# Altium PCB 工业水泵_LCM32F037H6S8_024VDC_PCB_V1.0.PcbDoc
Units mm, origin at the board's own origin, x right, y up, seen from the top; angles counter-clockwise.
Board outline 152.4 x 101.6 mm, 2 copper layers (Top Layer, Bottom Layer); 70 components, 49 nets, 180 pads, 167 vias.
Unrouted connection lines stored in the file: 17.
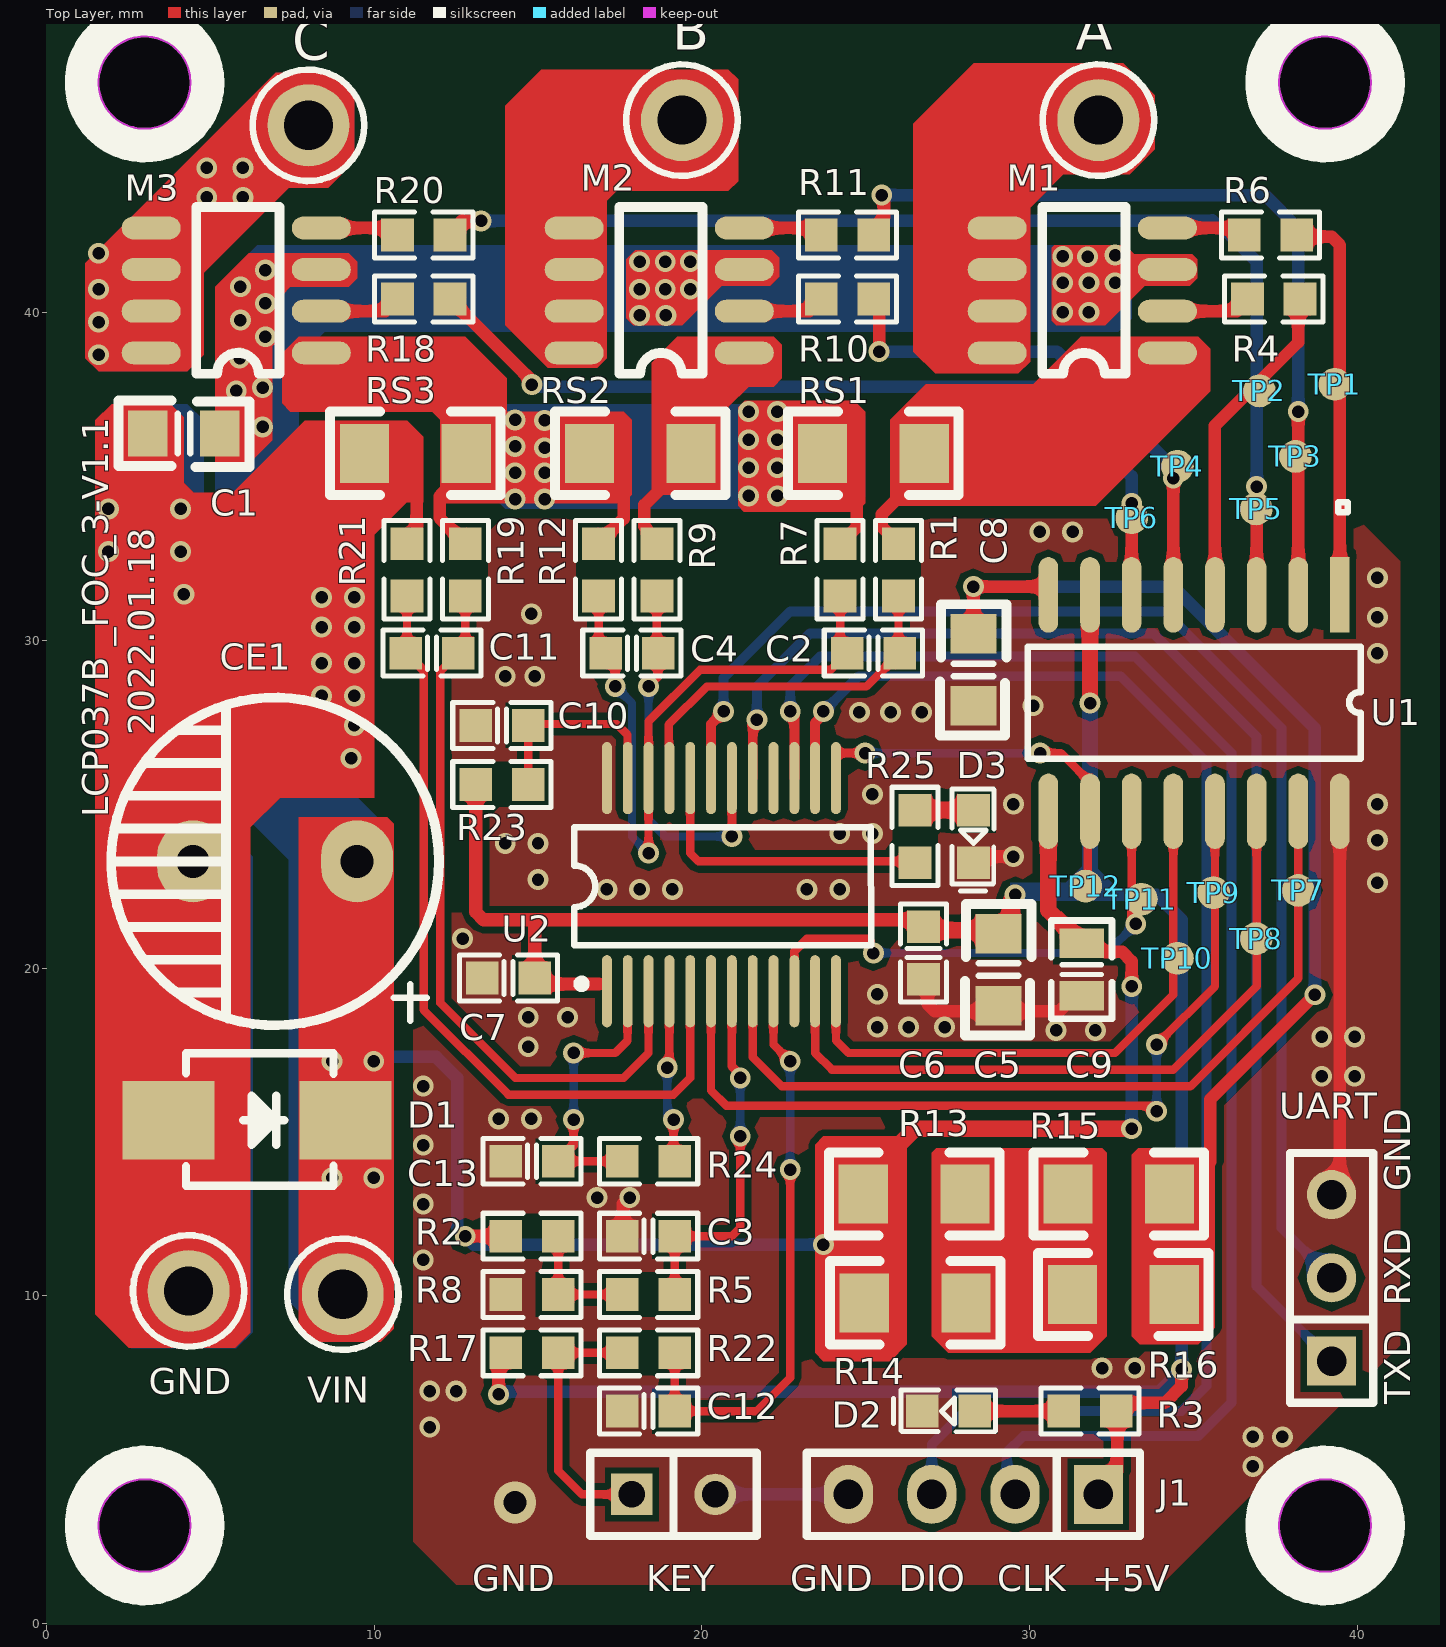
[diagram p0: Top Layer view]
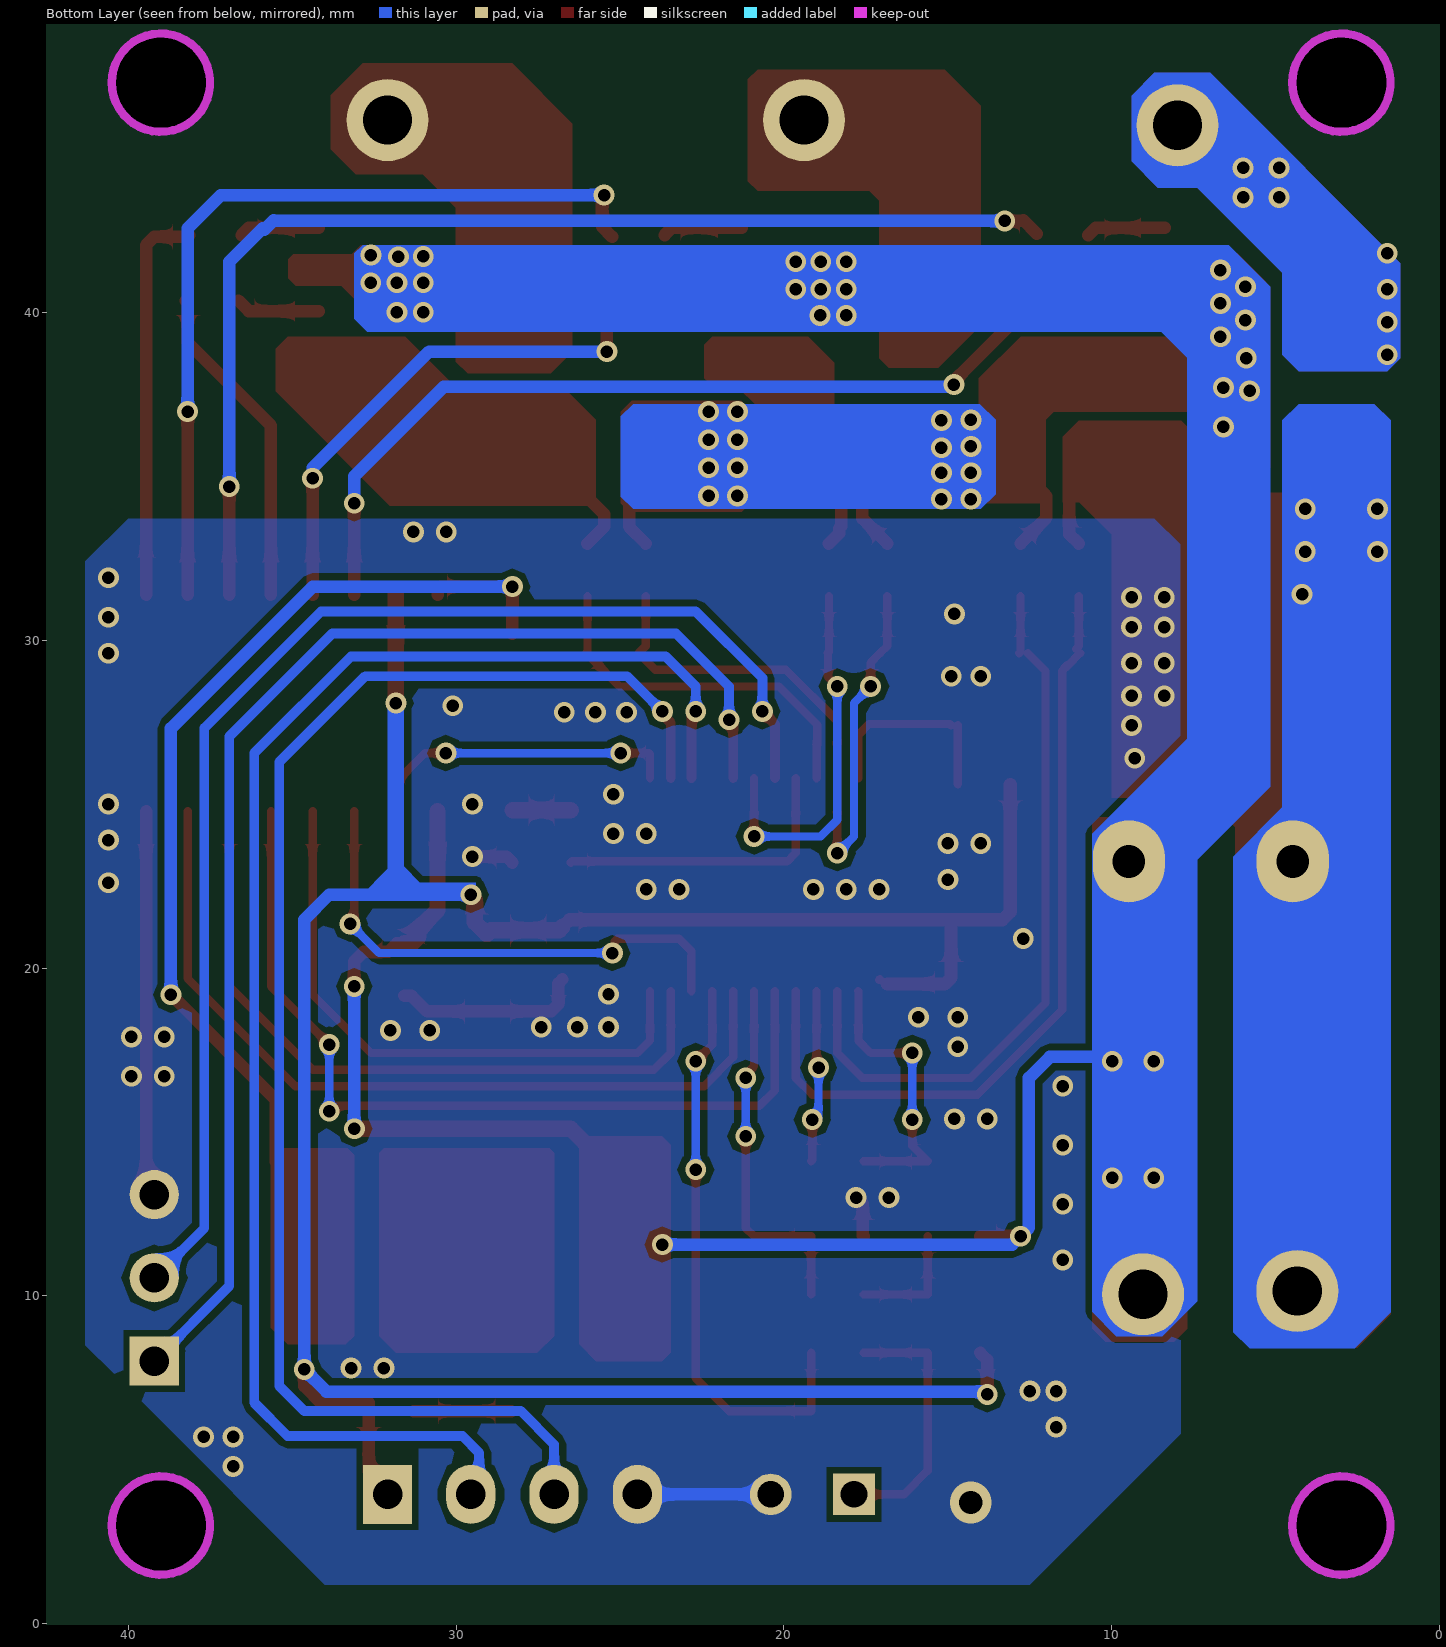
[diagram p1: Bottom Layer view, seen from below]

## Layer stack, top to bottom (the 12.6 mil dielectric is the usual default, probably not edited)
Top Solder: solder mask 0.0102, Solder Resist, Dk 3.5
Top Layer: signal copper 0.0356
Dielectric 1: dielectric 0.32, FR-4, Dk 4.8
Bottom Layer: signal copper 0.0356
Bottom Solder: solder mask 0.0102, Solder Resist, Dk 3.5

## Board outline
-37.635,-38.724 114.765,-38.724 114.765,62.876 -37.635,62.876
cut-out: 1.5,3 ccw(c3,3) 3,1.5 ccw(c3,3) 4.5,3 ccw(c3,3) 3,4.5 ccw(c3,3)
cut-out: 37.5,3 ccw(c39,3) 39,1.5 ccw(c39,3) 40.5,3 ccw(c39,3) 39,4.5 ccw(c39,3)
cut-out: 37.5,47 ccw(c39,47) 39,45.5 ccw(c39,47) 40.5,47 ccw(c39,47) 39,48.5 ccw(c39,47)
cut-out: 1.5,47 ccw(c3,47) 3,45.5 ccw(c3,47) 4.5,47 ccw(c3,47) 3,48.5 ccw(c3,47)

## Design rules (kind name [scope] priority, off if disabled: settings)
Clearance [All] p1: gap=0.2 ignorepadtopadclearanceinfootprint=FALSE
ComponentClearance [All] p1: gap=0.15 collisioncheckmode=3 verticalgap=0.254 showdistances=FALSE
Height [All] p1: minheight=0 maxheight=200 prefheight=12.7
MinimumSolderMaskSliver [All] p1: minsoldermaskwidth=0.12
PlaneConnect [All] p1: planeconnectstyle=Direct reliefexpansion=0.508 reliefentries=4 reliefconductorwidth=0.254 reliefairgap=0.254
PolygonConnect [All] p1: connectstyle=Direct reliefconductorwidth=0.254 reliefentries=4 polygonreliefangle="90 Angle" airgapwidth=0.254
RoutingVias [All] p1: holewidth=0.381 width=0.635 viastyle="Through Hole" minholewidth=0.305 minwidth=0.508 maxholewidth=0.711 maxwidth=1.27
SilkToSilkClearance [All] p1: silktosilkclearance=0.1
SilkToSolderMaskClearance [IsPad] p1: minsilkscreentomaskgap=0.05 clearancetoexposedcopper=TRUE
SolderMaskExpansion [All] p1: expansion=0.102
Width [All] p1: maxlimit=1.27 minlimit=0.254 preferedwidth=0.381
24 further rules are at their usual default settings.

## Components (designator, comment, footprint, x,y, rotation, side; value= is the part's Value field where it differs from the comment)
A "CON1" CON-F1.5 32.088,45.858 r90 top
B "CON1" CON-F1.5 19.388,45.858 r90 top
C "CON1" CON-F1.5 8,45.7 r90 top
C1 "0.1uF/50V 0805" C0805 4.2,36.3 r180 top
C2 "100pF" C0603 25.23,29.602 r0 top
C3 "10nF" C0603 18.372,11.822 r180 top
C4 "100pF" C0603 17.864,29.602 r0 top
C5 "10uF" C0805 29.04,19.95 r90 top
C6 "0.1uF" C0603 26.754,20.458 r90 top
C7 "0.1uF" C0603 14.1,19.7 r180 top
C8 "1uF/50V/0805" C0805 28.278,29.094 r90 top
C9 "0.1uF/50V 0805" C0805X 31.58,19.95 r270 top
C10 "0.1uF" C0603 13.9,27.4 r180 top
C11 "100pF" C0603 11.768,29.602 r0 top
C12 "10nF" C0603 18.372,6.488 r180 top
C13 "2.2uF" C0603 14.816,14.108 r180 top
CE1 "470uF/35V" C-DR10-5 6.982,23.252 r270 top
D1 "28V" SMB 6.434,15.378 r0 top
D2 "" 0603-LED/H 27.516,6.488 r0 top
D3 "" 0603-LED/H 28.278,24.014 r90 top
GND "CON1" CON-F1.5 4.346,10.152 r0 top
J1 "CON4" SIP4 32.088,3.948 r180 top
KEY "CON2" SIP2 17.864,3.948 r0 top
M1 "BPM0405CG" SOP-8S 34.193,38.755 r180 top locked
M2 "BPM0405CG" SOP-8S 21.293,38.755 r180 top locked
M3 "BPM0405CG" SOP-8S 8.393,38.755 r180 top locked
R1 "68R 1% 0603" R0603 25.992,32.142 r90 top
R2 "100K 1% 0603" R0603 14.816,11.822 r0 top
R3 "1K" R0603 31.834,6.488 r0 top
R4 "51R" R0603 37.438,40.4 r180 top
R5 "1K" R0603 18.372,10.044 r0 top
R6 "51R" R0603 37.338,42.354 r180 top
R7 "68R 1% 0603" R0603 24.214,32.142 r90 top
R8 "10K 1% 0603" R0603 14.816,10.044 r180 top
R9 "68R 1% 0603" R0603 18.626,32.142 r90 top
R10 "51R" R0603 24.438,40.4 r180 top
R11 "51R" R0603 24.438,42.354 r180 top
R12 "68R 1% 0603" R0603 16.848,32.142 r90 top
R13 "1K/1206" 1206/X 26.468,13.108 r180 top
R14 "1K/1206" 1206/X 26.5,9.79 r180 top
R15 "1K/1206" 1206/X 32.712,13.108 r180 top
R16 "1K/1206" 1206/X 32.85,10.044 r180 top
R17 "10K" R0603 14.816,8.266 r0 top
R18 "51R" R0603 11.514,40.4 r180 top
R19 "68R 1% 0603" R0603 12.784,32.142 r90 top
R20 "51R" R0603 11.514,42.354 r180 top
R21 "68R 1% 0603" R0603 11.006,32.142 r90 top
R22 "1K" R0603 18.372,8.266 r180 top
R23 "10K" R0603 13.9,25.6 r0 top
R24 "10K" R0603 18.372,14.108 r180 top
R25 "1K" R0603 26.5,24.014 r270 top
RS1 "0.05R 1206" 1206/X 25.23,35.698 r180 top
RS2 "0.05R 1206" 1206/X 18.118,35.698 r180 top
RS3 "0.05R 1206" 1206/X 11.26,35.698 r180 top
TP1 "TestPoint" TP_1.0-A 39.3,37.8 r90 top
TP2 "TestPoint" TP_1.0-A 37,37.6 r90 top
TP3 "TestPoint" TP_1.0-A 38.1,35.6 r90 top
TP4 "TestPoint" TP_1.0-A 34.5,35.3 r90 top
TP5 "TestPoint" TP_1.0-A 36.9,34 r90 top
TP6 "TestPoint" TP_1.0-A 33.104,33.73 r90 top
TP7 "TestPoint" TP_1.0-A 38.184,22.365 r90 top
TP8 "TestPoint" TP_1.0-A 36.9,20.9 r90 top
TP9 "TestPoint" TP_1.0-A 35.6,22.3 r90 top
TP10 "TestPoint" TP_1.0-A 34.5,20.3 r90 top
TP11 "TestPoint" TP_1.0-A 33.4,22.1 r90 top
TP12 "TestPoint" TP_1.0-A 31.7,22.5 r90 top
U1 "LCM2103" SOP16 39.454,31.38 r270 top
U2 "LCM32F037H6S8" SSOP24-H 17.102,19.292 r0 top locked
UART "CON3" SIP3 39.2,8.012 r90 top
VIN "CON1" CON-F1.5 9.046,10.052 r180 top

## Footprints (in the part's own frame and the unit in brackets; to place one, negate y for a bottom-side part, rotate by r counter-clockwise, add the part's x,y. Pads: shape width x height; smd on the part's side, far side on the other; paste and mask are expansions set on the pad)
0603-LED/H [mm]
  rect 1x1 smd: 1(-0.8,0) 2(0.8,0)
  silkscreen extent -1.67,-0.63 1.44,0.65
1206/X [mm]
  rect 1.5x1.8 smd: 1(-1.55,0) 2(1.55,0)
  silkscreen extent -2.6,-1.27 2.6,1.27
C0603 [mm]
  rect 1x1 smd: 1(-0.8,0) 2(0.8,0)
  silkscreen extent -1.5,-0.7 1.5,0.7
C0805 [mm]
  rect 1.2x1.4 smd: 1(-1.1,0) 2(1.1,0)
  silkscreen extent -2,-1.01 2,1.02
C0805X [mm]
  rect 0.9x1.35 smd: 1(-0.8,0) 2(0.8,0)
  silkscreen extent -1.5,-0.92 1.5,0.92
C-DR10-5 [mm]
  oval 2.5x2.2 hole 1: 1(0,2.5) 2(0,-2.5)
  silkscreen extent -5,-5 5,5
CON-F1.5 [mm]
  round 2.5 hole 1.5: 1(0,0)
  silkscreen extent -1.7,-1.7 1.7,1.7
R0603 [mm]
  rect 1x1 smd: 1(-0.8,0) 2(0.8,0)
  silkscreen extent -1.5,-0.7 1.5,0.7
SIP2 [mil]
  rect 50x50 hole 32: 1(0,0)
  round 50 hole 32: 2(100,0)
  silkscreen extent -50,-50 150,50
SIP3 [mm]
  rect 1.5x1.5 hole 0.9: 1(0,0)
  round 1.5 hole 0.9: 2(2.54,0) 3(5.08,0)
  silkscreen extent -1.27,-1.27 6.35,1.27
SIP4 [mm]
  rect 1.5x1.8 hole 0.9: 1(0,0)
  oval 1.5x1.8 hole 0.9: 2(2.54,0) 3(5.08,0) 4(7.62,0)
  silkscreen extent -1.27,-1.27 8.89,1.27
SMB [mm]
  rect 2.8x2.4 smd: 1(-2.7,-0.02) 2(2.7,-0.02)
  silkscreen extent -2.17,-2.02 2.33,2.02
SOP16 [mm]
  rect 2.3x0.6 smd: 1(0,0)
  oval 2.3x0.6 smd: 2(0,-1.27) 3(0,-2.54) 4(0,-3.81) 5(0,-5.08) 6(0,-6.35) 7(0,-7.62) 8(0,-8.89) 9(6.6,-8.89) 10(6.6,-7.62) 11(6.6,-6.35) 12(6.6,-5.08) 13(6.6,-3.81) 14(6.6,-2.54) 15(6.6,-1.27) 16(6.6,0)
  silkscreen extent 1.58,-9.53 5,0.64
SOP-8S [mm]
  oval 1.8x0.7 smd: 1(0.001,-0.005) 2(0.001,-1.275) 3(0.001,-2.545) 4(0.001,-3.815) 5(5.189,-3.815) 6(5.189,-2.545) 7(5.189,-1.275) 8(5.189,-0.005)
  silkscreen extent 1.27,-4.45 3.81,0.63
SSOP24-H [mm]
  oval 0.3x2.2 smd: 1(0,0) 2(0.635,0) 3(1.27,0) 4(1.905,0) 5(2.54,0) 6(3.175,0) 7(3.81,0) 8(4.445,0) 9(5.08,0) 10(5.715,0) 11(6.35,0) 12(6.985,0) 13(6.985,6.5) 14(6.35,6.5) 15(5.715,6.5) 16(5.08,6.5) 17(4.445,6.5) 18(3.81,6.5) 19(3.175,6.5) 20(2.54,6.5) 21(1.905,6.5) 22(1.27,6.5) 23(0.635,6.5) 24(0,6.5)
  silkscreen extent -0.99,0.1 8.06,5
TP_1.0-A [mm] "无丝印"
  round 1 smd: 1(0,0)

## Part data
A B C GND KEY UART VIN: "Connector"
C1 C2 C4 C9 C11: library part C-0603-104K50-X7R, "贴片电容", MPN1=CC0603KRX7R9BB104, MPN2=0603B104K500CT
C3 C5 C6 C8 C12: library part CAP, "Capacitor"
C7 C10 C13: library part CAP
CE1: library part CAP_ELECTRO, "Electrolytic Capacitor"
D1: library part "D Zener", "稳压管"
D2 D3: library part LED, "LED"
R1 R7 R9 R12 R19 R21 RS1 RS2 RS3: library part R-0603-10K-J, "贴片电阻"
R2 R3 R4 R5 R6 R8 R10 R11 R13 R14 R15 R16 R17 R18 R20 R22 R23 R24 R25: library part RES
TP1 TP2 TP3 TP4 TP5 TP6 TP7 TP8 TP9 TP10 TP11 TP12: "Testpoint"
U1: library part MX8324
U2: library part LM32

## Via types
v1: diameter 0.635, hole 0.381, Top Layer to Bottom Layer, tented both sides, 166 vias
v2: diameter 1.27, hole 0.711, Top Layer to Bottom Layer, 1 vias

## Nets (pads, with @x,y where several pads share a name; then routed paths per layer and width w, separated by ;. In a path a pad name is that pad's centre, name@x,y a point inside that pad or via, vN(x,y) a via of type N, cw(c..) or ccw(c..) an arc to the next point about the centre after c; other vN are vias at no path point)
+5V: C5.2 C6.2 C7.1 J1.1 R3.2 R17.1 R23.1 U1.7 U2.1 | length 81.6
  Top Layer w0.254: U2.1@17.081,19.658 U2.1@17.102,19.637
  Top Layer w0.381: v1(13.8,6.996) 13.8,8.05 R17.1 ; J1.1 32.088,4.098 32.648,4.658 32.665,4.658 32.665,6.742 34.12,6.742 34.628,7.25 v1(34.628,7.758)
  Top Layer w0.4: R23.1 13.1,21.708 13.334,21.474 14.8,21.474 ; 16.863,19.511 15.089,19.511 C7.1 14.9,21.374 14.8,21.474 ; C6.2 26.538,21.474 14.8,21.474
  Top Layer w0.5: C6.2 26.858,21.154 28.936,21.154 C5.2 29.079,21.05 29.429,21.4 29.429,22.081 29.548,22.199 v1(29.548,22.236) ; v1(31.834,28.078) U1.7
  Bottom Layer w0.381: v1(13.8,6.996) 13.887,7.083 33.953,7.083 v1(34.628,7.758) 34.628,21.474 33.866,22.236 v1(29.548,22.236)
  Bottom Layer w0.5: 31.834,22.49 v1(31.834,28.078)
+24V: C1.1 C9.1 CE1.1 D1.2 M1.3 M2.3 M3.3 R2.1 R13.2 R14.2 U1.9 VIN.1 | length 103.7
  Top Layer w0.254: M3.3@8.385,41.293 M3.3 ; M2.3@21.285,41.293 M2.3 ; 25,14.3 25.6,14.3 ; M1.3@34.178,41.286 M1.3
  Top Layer w0.381: v1(12.784,11.822) R2.1 ; v1(23.706,11.568) 24.815,11.568 24.918,11.465 ; R13.2 24.918,11.465 ; R14.2 24.918,9.822 24.918,11.465 ; C9.1 31.805,20.75 32.065,20.491 32.818,20.491 33.104,20.204 v1(33.104,19.442)
  Top Layer w0.5: 25.6,14.3 25.7,14.3 26.5,15.1 v1(33.1,15.1) ; U1.9 30.564,21.766 31.155,21.175 31.155,20.95 31.355,20.75 C9.1
  Bottom Layer w0.254: VIN.1 9.476,10.482 9.476,11.318 9.482,11.324 9.482,17.288 CE1.1 9.482,23.402 5.672,27.212 6.688,28.228 v1(6.688,41.286) 6.942,41.54 v1(19.642,41.54) 31.58,41.54 31.682,41.642 v1@31.859,41.642
  Bottom Layer w0.381: 9.482,17.288 11.89,17.288 12.53,16.648 12.53,12.076 v1(12.784,11.822) 13.038,11.568 v1(23.706,11.568) ; v1@33.104,15.1 v1(33.104,19.442)
  other v1: 8.72,13.6 9.99,13.6 8.72,17.156 9.99,17.156 6.6,36.5 5.8,37.6 6.6,37.7 5.9,38.6 6.688,39.254 5.926,39.762 18.1,39.9 18.9,39.9 31,40 31.8,40 6.688,40.27 18.1,40.7 18.88,40.7 19.642,40.7 5.926,40.778 31,40.9 31.8,40.9 32.6,40.9 18.1,41.54 18.88,41.54 31,41.7 31.758,41.692 32.596,41.743
AH: TP8.1 U1.14 U2.11 | length 21.9
  Top Layer w0.254: U2.11 23.452,17.41 23.96,16.902 34.374,16.902 36.914,19.442 U1.14
AHO: R6.1 TP1.1 U1.1 | length 12.1
  Top Layer w0.381: R6.1 38.19,42.302 39.2,42.302 39.454,42.048 U1.1
AL: TP7.1 U1.15 U2.8 | length 25.5
  Top Layer w0.254: U2.8 21.547,17.283 22.436,16.394 34.894,16.394 38.184,19.684 TP7.1 U1.15
ALO: R4.1 TP2.1 U1.4 | length 10
  Top Layer w0.381: U1.4 35.644,36.544 38.184,39.084 38.184,40.3 R4.1@38.238,40.354
BH: TP10.1 U1.12 U2.12 | length 18.3
  Top Layer w0.254: U2.12 24.087,17.791 24.468,17.41 32.596,17.41 34.374,19.188 U1.12
BHO: R11.1 TP3.1 U1.2 | length 25.7
  Top Layer w0.381: R11.1@25.238,42.3 25.548,42.61 25.548,43.508 v1(25.484,43.572) ; U1.2 v1(38.184,36.968)
  Bottom Layer w0.381: v1(25.484,43.572) 37.168,43.572 38.184,42.556 v1(38.184,36.968)
BL: TP9.1 U1.13 U2.6 | length 26.8
  Top Layer w0.254: U2.6 20.277,16.267 20.744,15.8 33.698,15.8 v1(33.866,15.632) ; v1(33.866,17.664) 35.644,19.442 U1.13
  Bottom Layer w0.254: v1(33.866,15.632) v1(33.866,17.664)
BLO: R10.1 TP4.1 U1.5 | length 16
  Top Layer w0.381: R10.1 25.4,40.238 v1(25.4,38.8) ; U1.5 v1(34.374,34.936)
  Bottom Layer w0.381: v1(25.4,38.8) 30.824,38.8 34.374,35.25 v1(34.374,34.936)
BUZ: U2.16
CH: TP12.1 U1.10 U2.13 | length 12.1
  Top Layer w0.254: U2.13 24.087,26.533 24.108,26.554 v1(24.976,26.554) ; v1(30.31,26.554) 30.946,26.554 31.814,25.686 31.814,24.8 U1.10 31.768,24.714 31.768,22.568 TP12.1
  Bottom Layer w0.254: v1(24.976,26.554) v1(30.31,26.554)
CHO: R20.1 TP5.1 U1.3 | length 35.5
  Top Layer w0.381: R20.1@12.292,42.4 12.702,42.81 12.727,42.785 v1(13.267,42.785) ; U1.3 v1(36.914,34.682)
  Bottom Layer w0.381: v1(13.267,42.785) 35.532,42.785 35.557,42.81 35.855,42.513 35.898,42.556 36.914,41.54 v1(36.914,34.682)
CL: TP11.1 U1.11 U2.10 | length 17.1
  Top Layer w0.254: U2.10@22.826,20.367 22.826,19.301 U2.10 22.817,20.512 23.198,20.893 25.081,20.893 25.157,20.817 25.157,20.531 v1(25.23,20.458) ; U1.11 33.104,21.474 v1(33.231,21.347)
  Bottom Layer w0.254: v1(25.23,20.458) 32.342,20.458 v1(33.231,21.347)
CLO: R18.1 TP6.1 U1.6 | length 26.7
  Top Layer w0.381: R18.1 14.816,37.898 v1(14.816,37.793) ; U1.6 TP6.1 v1(33.104,34.174)
  Bottom Layer w0.381: v1(14.816,37.793) 14.879,37.73 30.37,37.73 33.104,34.996 v1(33.104,34.174)
GND: C1.2 C3.2 C5.1 C6.1 C7.2 C8.1 C9.2 C10.2 C12.2 C13.2 CE1.2 D1.1 D2.1 D3.1 GND.1 J1.4 KEY.2 R8.2 R21.2 RS3.2 U1.16 U2.24 UART.3 | length 44.1
  Top Layer w0.381: 4.2,28.6 9.1,28.6 ; RS3.2@10.218,35.698 11.3,34.616 11.3,33.236 R21.2 ; C3.2 17.591,11.841 17.591,12.819 v1@17.61,12.838 ; C6.1 26.878,19.534 26.878,18.903 27.102,18.68 30.885,18.68 31.355,19.15 C9.2 ; D3.1 28.464,23.4 v1(29.5,23.4) ; UART.3 39.2,13.395 39.454,13.649 U1.16
  Bottom Layer w0.381: 4.346,11.422 4.482,11.558 CE1.2 ; KEY.2 J1.4
  other v1: 36.8,4.8 36.8,5.7 37.7,5.7 11.7,6 11.7,7.1 12.5,7.1 32.2,7.8 33.2,7.8 11.5,11.1 11.5,12.8 16.8,13 17.8,13 11.5,14.6 13.8,15.4 14.8,15.4 11.5,16.4 38.9,16.7 39.9,16.7 14.7,17.6 38.9,17.9 39.9,17.9 30.8,18.1 32,18.1 25.35,18.2 26.3,18.2 27.4,18.2 14.7,18.5 15.9,18.5 25.35,19.2 12.7,20.9 17.1,22.4 18.1,22.4 19.1,22.4 23.2,22.4 24.2,22.4 40.6,22.6 15,22.7 14,23.8 15,23.8 40.6,23.9 24.2,24.1 25.2,24.1 29.5,25 40.6,25 25.2,25.3 9.3,26.4 9.4,27.4 24.8,27.8 25.75,27.8 26.7,27.8 30.1,28 8.4,28.3 9.4,28.3 14,28.9 14.9,28.9 8.4,29.3 9.4,29.3 40.6,29.6 8.4,30.4 9.4,30.4 40.6,30.7 14.8,30.8 8.4,31.3 9.4,31.3 4.2,31.4 40.6,31.9 1.9,32.7 4.1,32.7 30.3,33.3 31.3,33.3 1.9,34 4.1,34
  other v2: 14.3,3.7
KEY: C12.1 R22.1 U2.9 | length 17.7
  Top Layer w0.254: R22.1 C12.1 21.674,6.488 22.69,7.504 v1(22.69,13.854) ; U2.9 22.182,17.664 v1(22.69,17.156)
  Bottom Layer w0.254: v1(22.69,13.854) v1(22.69,17.156)
LED: R25.2 U2.20 | length 9.3
  Top Layer w0.254: U2.20 19.642,23.506 19.896,23.252 26.462,23.252 R25.2 R25.2@26.508,23.222
NetA_1: A.1 M1.5 M1.6 M1.7 M1.8 | length 3.8
  Top Layer w0.381: M1.8 M1.7 M1.6 M1.5
NetB_1: B.1 M2.5 M2.6 M2.7 M2.8 | length 3.8
  Top Layer w0.381: M2.8 M2.7 M2.6 M2.5
NetC_1: C.1 M3.5 M3.6 M3.7 M3.8
  other v1: 1.6,38.7 1.6,39.7 1.6,40.7 1.6,41.8 4.9,43.5 6,43.5 4.9,44.4 6,44.4
NetD2_2: D2.2 R3.1 | length 3
  Top Layer w0.381: D2.2 R3.1@31.288,6.488
NetD3_2: D3.2 R25.1 | length 1.8
  Top Layer w0.5: R25.1 D3.2
NetKEY_1: KEY.1 R17.2 R22.2 | length 8.1
  Top Layer w0.254: R22.2 R17.2 15.616,4.672 16.34,3.948 KEY.1
NetM1_1: M1.1 R1.2 RS1.1 | length 12.4
  Top Layer w0.381: R1.2 25.484,33.45 25.484,33.846 26.78,35.142 RS1.1 31.13,35.698 33.646,38.214 33.646,38.613 33.794,38.76 M1.1
NetM1_2: M1.2 R4.2 | length 2.6
  Top Layer w0.381: M1.2 36.314,40.03 R4.2@36.638,40.354
NetM1_4: M1.4 R6.2 | length 2.4
  Top Layer w0.381: M1.4 36.322,42.57 R6.2
NetM2_1: M2.1 R9.2 RS2.1 | length 7.9
  Top Layer w0.381: R9.2 18.316,33.252 18.316,33.403 18.245,33.475 18.245,34.125 19.668,35.548 RS2.1 19.668,38.264 20.164,38.76 M2.1
NetM2_2: M2.2 R10.2 | length 2.5
  Top Layer w0.381: M2.2 23.268,40.03 R10.2
NetM2_4: M2.4 R11.2 | length 2.4
  Top Layer w0.381: M2.4 23.422,42.57 R11.2
NetM3_1: M3.1 R7.2 R12.2 R19.2 RS1.2 RS2.2 RS3.1 | length 14
  Top Layer w0.381: R19.2 12,33.726 12,34.38 12.608,34.989 12.758,34.989 13.318,35.548 13.318,35.698 RS2.2 16.568,35.548 17.128,34.989 17.278,34.989 17.61,34.656 17.61,33.704 R12.2 ; RS1.2 24.722,34.656 24.722,33.45 R7.2
  other v1: 14.3,34.3 15.2,34.3 21.42,34.4 22.3,34.4 14.3,35.105 15.2,35.105 21.42,35.256 22.3,35.256 15.2,35.867 14.3,35.909 21.42,36.112 22.3,36.112 15.2,36.7 14.3,36.714 21.42,36.968 22.3,36.968
NetM3_2: M3.2 R18.2 | length 2.5
  Top Layer w0.381: M3.2 10.344,40.03 R18.2
NetM3_4: M3.4 R20.2 | length 2.4
  Top Layer w0.381: M3.4 10.498,42.57 R20.2
NetR2_2: R2.2 R5.1 R8.1 | length 3.7
  Top Layer w0.254: R2.2 R8.1 R5.1
NetR13_1: R13.1 R14.1 R15.2 R16.2 | length 9.6
  Top Layer w0.381: R16.2@31.162,9.708 31.08,9.79 R14.1 28.018,9.822 R13.1 R15.2
NRST: C10.1 R23.2 U2.23 | length 6.1
  Top Layer w0.254: R23.2 C10.1 ; C10.1@14.9,27.4 14.943,27.443 17.4,27.443 17.728,27.115 17.728,25.801 U2.23
OPA0N: C11.1 R21.1 U2.5 | length 25.2
  Top Layer w0.254: C11.1 C11.1@11.341,29.229 ; R21.1 11.006,29.818 C11.1@11.095,29.729 ; C11.1@11.155,29.416 C11.1@11.341,29.229 ; C11.1@11.448,29.16 11.379,29.229 C11.1@11.341,29.229 ; U2.5 19.642,16.648 19.134,16.14 14.098,16.14 11.514,18.724 11.514,29.056 C11.1@11.341,29.229
OPA0P: C11.2 R19.1 U2.3 | length 22.1
  Top Layer w0.254: C11.2 12.022,29.056 12.022,18.934 14.308,16.648 17.61,16.648 18.372,17.41 U2.3 ; R19.1 12.784,29.64 C11.2@12.822,29.602
OPA0P-out: R24.1 U2.4 | length 5.2
  Top Layer w0.254: v1(18.944,16.966) 19.007,17.029 U2.4 ; v1(19.134,15.378) 19.134,14.146 R24.1
  Bottom Layer w0.254: v1@18.944,15.442 v1(18.944,16.966)
OPA0P-out-LDF: C13.1 R24.2 U2.2 | length 8.8
  Top Layer w0.254: v1(16.086,15.378) 16.086,14.578 C13.1 R24.2 ; v1(16.086,17.41) 17.356,17.41 17.728,17.782 17.728,19.283 U2.2
  Bottom Layer w0.254: v1(16.086,15.378) v1(16.086,17.41)
OPA1N/OPA2N: C2.1 C4.1 R7.1 R12.1 U2.22 | length 21.2
  Top Layer w0.254: R12.1 16.848,29.818 C4.1 17.356,29.31 v1(17.356,28.586) ; v1(18.372,23.506) U2.22 18.372,27.526 19.94,29.094 23.922,29.094 C2.1 24.214,29.818 R7.1
  Bottom Layer w0.254: v1(17.356,28.586) 17.864,28.078 17.864,24.014 v1(18.372,23.506)
OPA1P: C2.2 R1.1 U2.21 | length 11.3
  Top Layer w0.254: U2.21 18.998,25.801 18.998,26.783 18.985,26.796 18.985,27.421 20.15,28.586 25.014,28.586 C2.2 25.992,29.64 R1.1
OPA2P: C4.2 R9.1 U2.18 | length 11.5
  Top Layer w0.254: v1(18.372,28.586) 18.656,28.87 18.656,29.594 C4.2 18.626,29.64 R9.1 ; v1(20.912,24.014) U2.18
  Bottom Layer w0.254: v1(18.372,28.586) 18.372,24.522 18.88,24.014 v1(20.912,24.014)
RXD: U2.19 UART.2 | length 39.9
  Top Layer w0.3: U2.19 20.277,27.443 v1(20.658,27.824)
  Bottom Layer w0.3: v1(20.658,27.824) 20.658,28.84 22.69,30.872 34.12,30.872 37.676,27.316 37.676,12.076 UART.2
SWCLK: J1.2 U2.15 | length 46.7
  Top Layer w0.3: v1(22.69,27.824) 22.781,27.824 22.817,27.86 U2.15
  Bottom Layer w0.3: v1(22.69,27.824) 22.69,28.586 23.604,29.5 33.206,29.5 36.152,26.554 36.152,6.742 35.136,5.726 29.802,5.726 29.294,5.218 29.294,4.677 29.548,4.423 J1.2
SWDIO: J1.3 U2.14 | length 45
  Top Layer w0.3: U2.14 23.452,27.481 23.706,27.735 v1(23.706,27.824)
  Bottom Layer w0.3: v1(23.706,27.824) 24.782,28.9 32.769,28.9 35.39,26.279 35.39,7.25 34.628,6.488 28.024,6.488 27.008,5.472 J1.3
TXD: U2.17 UART.1 | length 40.1
  Top Layer w0.3: U2.17 21.547,27.443 v1(21.674,27.57)
  Bottom Layer w0.3: v1(21.674,27.57) 21.674,28.586 23.288,30.2 33.776,30.2 36.914,27.062 36.914,10.298 UART.1
Vbus: C3.1 R5.2 U2.7 | length 11.2
  Top Layer w0.254: R5.2 C3.1 20.912,11.822 21.166,12.076 v1(21.166,14.87) ; U2.7 20.912,17.005 21.166,16.751 v1(21.166,16.648)
  Bottom Layer w0.254: v1(21.166,14.87) v1(21.166,16.648)
VCCP: C8.2 R15.1 R16.1 U1.8 | length 35.4
  Top Layer w0.381: C8.2 v1(28.278,31.634) 30.463,31.634 30.564,31.533 U1.8 ; R16.1 34.262,10.182 R15.1 34.508,13.108 35.5,14.1 35.5,15.996 v1(38.692,19.188)
  Bottom Layer w0.381: v1(28.278,31.634) 34.366,31.634 38.692,27.308 v1(38.692,19.188)

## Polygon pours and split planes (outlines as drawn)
GND on Top Layer "GND_L01_P000" (solid, remove dead copper, pour order 0): 13.9,33.7 40,33.7 41.3,32.4 41.3,8.5 34,1.2 12.5,1.2 11.2,2.5 11.2,31
GND on Bottom Layer "GND_L02_P002" (solid, remove dead copper, pour order 2): 8.7,33.7 40,33.7 41.3,32.4 41.3,8.5 34,1.2 12.5,1.2 7.9,5.8 7.9,32.9

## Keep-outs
Keep-Out Layer:
  circle w0.254: c3,3 r1.5
  circle w0.254: c39,3 r1.5
  circle w0.254: c39,47 r1.5
  circle w0.254: c3,47 r1.5

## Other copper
Top Layer:
  pour cut-out: 26.3,14.4 26.3,8.574 25.992,8.266 26.158,8.1 33.3,8.1 33.7,8.5 33.7,13.9 32.9,14.7 32.9,14.8 26.43,14.8 26.246,14.616
  region net NetC_1: 4.8,38.7 4.8,41.2 7.4,43.8 8.6,43.8 9.4,44.6 9.4,46.6 8.7,47.3 7,47.3 1.2,41.5 1.2,38.6 1.6,38.2 4.3,38.2
  region net NetB_1: 17.1,38.6 17.1,43.4 17.4,43.7 20.8,43.7 21.1,44 21.1,47.1 20.8,47.4 15.1,47.4 14,46.3 14,39.6 15.3,38.3 16.8,38.3
  region net +24V: 5.164,39.254 5.164,35.236 5.2,35.2 6,35.2 6.9,36.1 6.9,39.2 5.218,39.2
  region net GND: 1.5,30 1.5,36.7 2,37.2 3.8,37.2 4.2,36.8 4.2,34.8 4.5,34.5 6,34.5
  region: 1.8,37.3
  region net GND: 10,33.2 10,25.2 7.137,25.2 6.231,24.293 4.2,26.324 4.2,28.9 8.5,33.2
  region net GND: 6.231,8.876 6.231,24.293 5.774,24.751 5.774,28.974 11,34.2 11.5,34.2 11.5,36.2 11.011,36.689 7.889,36.689 1.5,30.3 1.5,9.441 2.522,8.418 5.774,8.418
  region net NetA_1: 27.11,38.136 26.449,38.797 26.449,45.749 28.285,47.585 32.85,47.585 33.815,46.62 33.815,44.969 33.053,44.207 31.021,44.207 30.005,43.191 30.005,38.492 29.65,38.136
  region net +24V: 32.901,42.048 33.18,41.769 34.958,41.769 35.111,41.616 35.111,41.032 34.882,40.803 33.503,40.803 32.3,39.6 30.8,39.6 30.666,39.734 30.666,41.966 30.748,42.048
  region net +24V: 22.131,41.896 22.36,41.667 22.36,41.083 22.08,40.803 20.603,40.803 19.4,39.6 17.9,39.6 17.686,39.814 17.686,41.616 17.966,41.896
  region: 17.864,41.794
  region: 18.118,42.048
  region net +24V: 6.18,41.794 9.228,41.794 9.482,41.54 9.482,41.032 9.228,40.778 7.45,40.778 7.196,40.524 7.196,39.254 6.688,38.746 5.672,38.746 5.164,39.254 5.164,40.778 5.418,41.032
  region net +24V: 7.704,8.996 7.704,24.6 10.4,24.6 10.6,24.4 10.6,9 10.2,8.6 8.1,8.6
  region net VCCP: 33.3,14.5 35.3,14.5 35.644,14.156 35.644,9.028 35.136,8.52 33.358,8.52 33.104,8.774 33.104,14.304
  region: 33.358,14.87
  region: 33.358,14.87
  region net NetR13_1: 27.146,14.5 32.204,14.5 32.342,14.362 32.342,8.774 31.834,8.266 27.516,8.266 27.008,8.774 27.008,14.362
  region net +24V: 25.992,14.87 26.246,14.616 26.246,8.52 25.738,8.012 23.706,8.012 23.452,8.266 23.452,14.616 23.706,14.87
  region net NetM1_1: 26.824,37.8 30.1,37.8 31.554,39.254 35.136,39.254 35.5,38.89 35.5,37.586 32.014,34.1 25.738,34.1 25.738,36.714
  region net NetM2_1: 20.8,34.6 20.8,37.11 21.42,37.73 22.182,37.73 22.436,37.984 22.436,39 22.182,39.254 19.254,39.254 18.462,38.462 18.462,34.592 18.626,34.428 20.628,34.428
  region net NetM3_1: 21.3,37.3 24.644,37.3 24.976,36.968 24.976,34.174 24.722,33.92 21.28,33.92 21.1,34.1 21.1,37.1
  region: 21.42,36.968
  region net NetM3_1: 12.022,36.968 17.61,36.968 17.864,36.714 17.864,34.428 17.61,34.174 12.022,34.174
  region net NetM3_1: 14.054,37.984
  region net NetM3_1: 7.704,39.254 12.784,39.254 14.054,37.984 14.054,34.936 13.8,34.682 12.53,34.682 12.022,35.19 12.022,36.714 11.768,36.968 7.45,36.968 7.196,37.222 7.196,38.746
Bottom Layer:
  region net +5V: 29.4,22.6 31.1,22.6 31.6,23.1 32,23.1 33,22.1 29.3,22.1 29.4,22.2
  region net GND: 2.6,8.4 5.8,8.4 6.3,8.9 6.3,23.4 4.8,24.9 4.8,36.7 4.3,37.2 2,37.2 1.5,36.7 1.5,9.5
  region net NetC_1: 4.8,38.7 4.8,41.2 7.4,43.8 8.6,43.8 9.4,44.6 9.4,46.6 8.7,47.3 7,47.3 1.2,41.5 1.2,38.6 1.6,38.2 4.3,38.2
  region: 6.104,8.444
  region net NetM3_1: 14.032,37.2 24.6,37.2 24.976,36.824 24.976,34.376 24.6,34 14,34 13.546,34.454 13.546,36.714
  region net +24V: 6.434,42.048 32.85,42.048 33.104,41.794 33.104,39.804 32.7,39.4 8.5,39.4 7.704,38.604 7.704,26.996 10.6,24.1 10.6,9.511 9.863,8.774 8.466,8.774 7.4,9.84 7.4,23.3 5.164,25.536 5.164,40.778

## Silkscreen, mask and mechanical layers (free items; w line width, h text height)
Top Overlay:
  circle w1: c3,3 r1.934
  circle w1: c39,3 r1.934
  circle w1: c39,47 r1.934
  circle w1: c3,47 r1.934
  lines w0.2: 10.6,19.1 11.6,19.1 ; 11.1,18.4 11.1,19.5 ; 39.4,33.9 39.4,34.2 39.7,34.2 39.7,33.9 39.4,33.9
  text "2022.01.18" at 3.3,27.1 h0.8 r90
  text "LCP037B _FOC_3-V1.1" at 1.9,24.6 h0.8 r90
  text "GND" at 41.6,13.2 h0.8 r90
  text "RXD" at 41.6,9.7 h0.8 r90
  text "TXD" at 41.6,6.7 h0.8 r90
  text "GND" at 13,1 h0.8
  text "GND" at 22.7,1 h0.8
  text "DIO" at 26,1 h0.8
  text "CLK" at 29,1 h0.8
  text "+5V" at 31.9,1 h0.8
Mechanical 1:
  lines w0.2: -0.1,0 -0.1,50 42,50 42,0 -0.1,0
